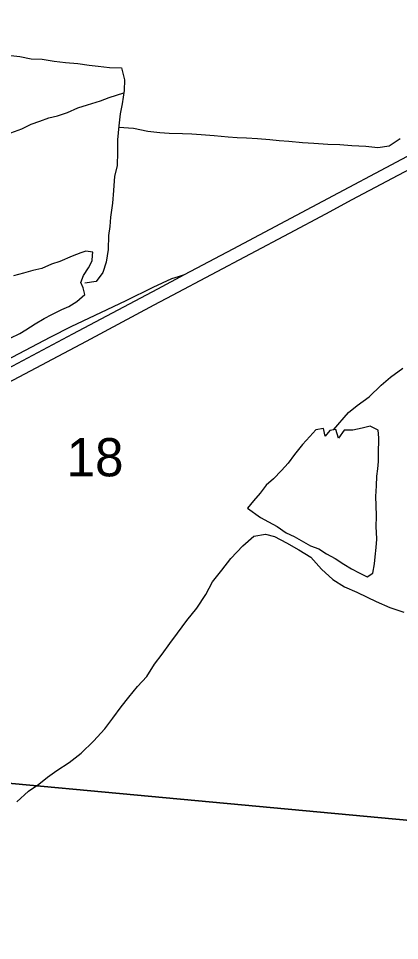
# Model space of a CAD drawing. Extents: x 0 to 680, y 0 to 440.
# Drawn here: x 195.36 to 201.89, y 247.33 to 263.13 of the extents above; entities that cross this region are included whole.
import ezdxf

# ---------------------------------------------------------------- set-up
doc = ezdxf.new("R2010")
doc.units = 0
for name, color, linetype in [('GM_X_Interstate_Route', 7, 'Continuous'), ('GM_X_Minor_Lake', 7, 'Continuous'), ('GM_X_Minor_River', 7, 'Continuous'), ('GM_X_Section', 7, 'Continuous'), ('GM_X_Section_Text', 7, 'Continuous')]:
    doc.layers.add(name, color=color, linetype=linetype)

msp = doc.modelspace()

# ---------------------------------------------------------------- linework, layer by layer
at = {"layer": 'GM_X_Interstate_Route'}
for points in [[(200.625, 259.782), (201.077, 260.025), (202.666, 260.868), (204.684, 261.941), (205.587, 262.419), (206.874, 263.105), (208.034, 263.72), (210.223, 264.886), (211.766, 265.712), (212.152, 265.918), (212.538, 266.125), (212.811, 266.27), (213.182, 266.467), (214.43, 267.124), (216.278, 268.103), (217.478, 268.747), (217.623, 268.823)], [(194.402, 256.721), (196.292, 257.724), (197.752, 258.499), (198.207, 258.741), (199.041, 259.183), (203.462, 261.536)], [(197.998, 258.386), (200.006, 259.449), (200.625, 259.782)], [(194.925, 257.155), (195.916, 257.677), (196.265, 257.852), (196.881, 258.143), (197.205, 258.296), (197.669, 258.524), (197.987, 258.672), (198.103, 258.711), (198.207, 258.741)], [(195.178, 256.888), (196.526, 257.603), (197.685, 258.221), (197.998, 258.386)]]:
    msp.add_lwpolyline(points, dxfattribs=at)
at = {"layer": 'GM_X_Minor_Lake'}
for points in [[(196.631, 259.073), (196.636, 259.128), (196.518, 259.142), (196.429, 259.113), (196.28, 259.056), (196.072, 258.963), (195.929, 258.918), (195.763, 258.848), (195.608, 258.809), (195.448, 258.763), (195.276, 258.718)], [(195.221, 257.651), (195.388, 257.732), (195.489, 257.796), (195.65, 257.895), (195.805, 257.988), (195.936, 258.058), (196.103, 258.144), (196.228, 258.196), (196.365, 258.278), (196.497, 258.401), (196.469, 258.514), (196.428, 258.603), (196.477, 258.727), (196.562, 258.857), (196.622, 258.974), (196.631, 259.073)], [(201.491, 254.607), (201.487, 254.787), (201.483, 254.941), (201.491, 255.119), (201.499, 255.285), (201.518, 255.41), (201.526, 255.54), (201.527, 255.664), (201.531, 255.943), (201.521, 256.074), (201.385, 256.141), (201.249, 256.107), (201.089, 256.073), (200.941, 256.075), (200.845, 255.94), (200.799, 256.089), (200.692, 256.072), (200.614, 255.972), (200.586, 256.103), (200.456, 256.081), (200.354, 255.964), (200.228, 255.829), (200.09, 255.658), (199.981, 255.511), (199.867, 255.382), (199.73, 255.242), (199.604, 255.13), (199.502, 254.995), (199.388, 254.866), (199.285, 254.737)], [(199.285, 254.737), (199.508, 254.58), (199.644, 254.507), (199.79, 254.422), (199.949, 254.314), (200.084, 254.253), (200.366, 254.095), (200.507, 254.04), (200.637, 253.955), (200.784, 253.876), (200.936, 253.78), (201.065, 253.701), (201.195, 253.628), (201.336, 253.561), (201.431, 253.625), (201.457, 253.785), (201.47, 253.904), (201.49, 254.064), (201.498, 254.206), (201.493, 254.325), (201.488, 254.414), (201.491, 254.607)]]:
    msp.add_lwpolyline(points, dxfattribs=at)
at = {"layer": 'GM_X_Minor_River'}
for points in [[(195.234, 262.497), (195.387, 262.477), (195.582, 262.439), (195.766, 262.431), (195.972, 262.399), (196.167, 262.378), (196.38, 262.358), (196.575, 262.332), (196.728, 262.312), (196.923, 262.292), (197.125, 262.284), (197.181, 262.081), (197.173, 261.898), (197.141, 261.667), (197.103, 261.495), (197.083, 261.288), (197.056, 261.051), (197.059, 260.843), (197.051, 260.606), (197.007, 260.429), (196.992, 260.18), (196.972, 259.967), (196.939, 259.724), (196.925, 259.564), (196.906, 259.41), (196.897, 259.173), (196.864, 258.954), (196.809, 258.776), (196.695, 258.624), (196.499, 258.596)], [(195.235, 261.168), (195.42, 261.237), (195.58, 261.318), (195.729, 261.37), (195.883, 261.427), (196.032, 261.461), (196.204, 261.518), (196.377, 261.599), (196.543, 261.65), (196.769, 261.719), (196.917, 261.776), (197.167, 261.856)], [(197.081, 261.269), (197.331, 261.249), (197.579, 261.199), (197.785, 261.178), (197.945, 261.165), (198.17, 261.156), (198.329, 261.154), (198.489, 261.14), (198.714, 261.126), (198.956, 261.099), (199.11, 261.091), (199.269, 261.083), (199.458, 261.075), (199.665, 261.055), (199.825, 261.041), (199.99, 261.027), (200.227, 261.006), (200.422, 260.992), (200.658, 260.977), (200.865, 260.969), (201.072, 260.955), (201.309, 260.94), (201.515, 260.919), (201.711, 260.947), (201.896, 261.075)], [(200.755, 256.082), (201.016, 256.377), (201.165, 256.499), (201.368, 256.645), (201.572, 256.844), (201.733, 256.985), (201.942, 257.136)], [(195.336, 249.708), (195.534, 249.89), (195.713, 250.012), (195.862, 250.129), (196.017, 250.245), (196.232, 250.379), (196.435, 250.543), (196.645, 250.748), (196.843, 250.959), (196.981, 251.141), (197.119, 251.335), (197.252, 251.5), (197.402, 251.682), (197.558, 251.852), (197.69, 252.064), (197.823, 252.234), (197.955, 252.422), (198.088, 252.599), (198.244, 252.816), (198.418, 253.027), (198.569, 253.257), (198.684, 253.475), (198.846, 253.675), (198.997, 253.874), (199.207, 254.091), (199.392, 254.261), (199.594, 254.294), (199.747, 254.251), (199.953, 254.142), (200.164, 254.026), (200.37, 253.899), (200.551, 253.695), (200.744, 253.515), (200.943, 253.388), (201.155, 253.297), (201.331, 253.211), (201.49, 253.138), (201.72, 253.035), (201.961, 252.955)]]:
    msp.add_lwpolyline(points, dxfattribs=at)
at = {"layer": 'GM_X_Section'}
for points in [[(190.144, 265.991), (204.975, 264.534), (203.666, 249.238), (188.668, 250.631)], [(188.668, 250.631), (203.666, 249.238), (202.126, 233.205), (187.086, 234.593)]]:
    msp.add_lwpolyline(points, close=True, dxfattribs=at)

# ---------------------------------------------------------------- texts
at = {"layer": 'GM_X_Section_Text'}
msp.add_text('18', height=0.6552, rotation=0, dxfattribs=at).set_placement((196.187, 255.284))

doc.saveas('drawing.dxf')
